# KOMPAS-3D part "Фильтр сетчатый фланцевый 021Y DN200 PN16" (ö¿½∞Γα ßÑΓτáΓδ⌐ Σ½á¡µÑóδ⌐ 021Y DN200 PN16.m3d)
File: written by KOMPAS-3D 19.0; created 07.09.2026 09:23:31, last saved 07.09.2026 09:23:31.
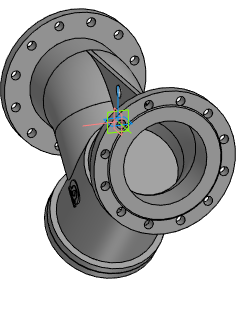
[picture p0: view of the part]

Document properties: Автор: Энергия; Полное имя файла: Z:\3.Личные\sachek\Dendor\_3D для проектировщиков\8.3 Фильтр сетчатый 021Y\021Y_STP\Фильтр сетчатый фланцевый 021Y DN200 PN16.m3d

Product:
- Part/product: Фильтр сетчатый фланцевый 021Y DN200 PN16

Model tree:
1. Операция без истории:1  (labels: Фильтр сетчатый фланцевый 021Y DN200 PN16)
